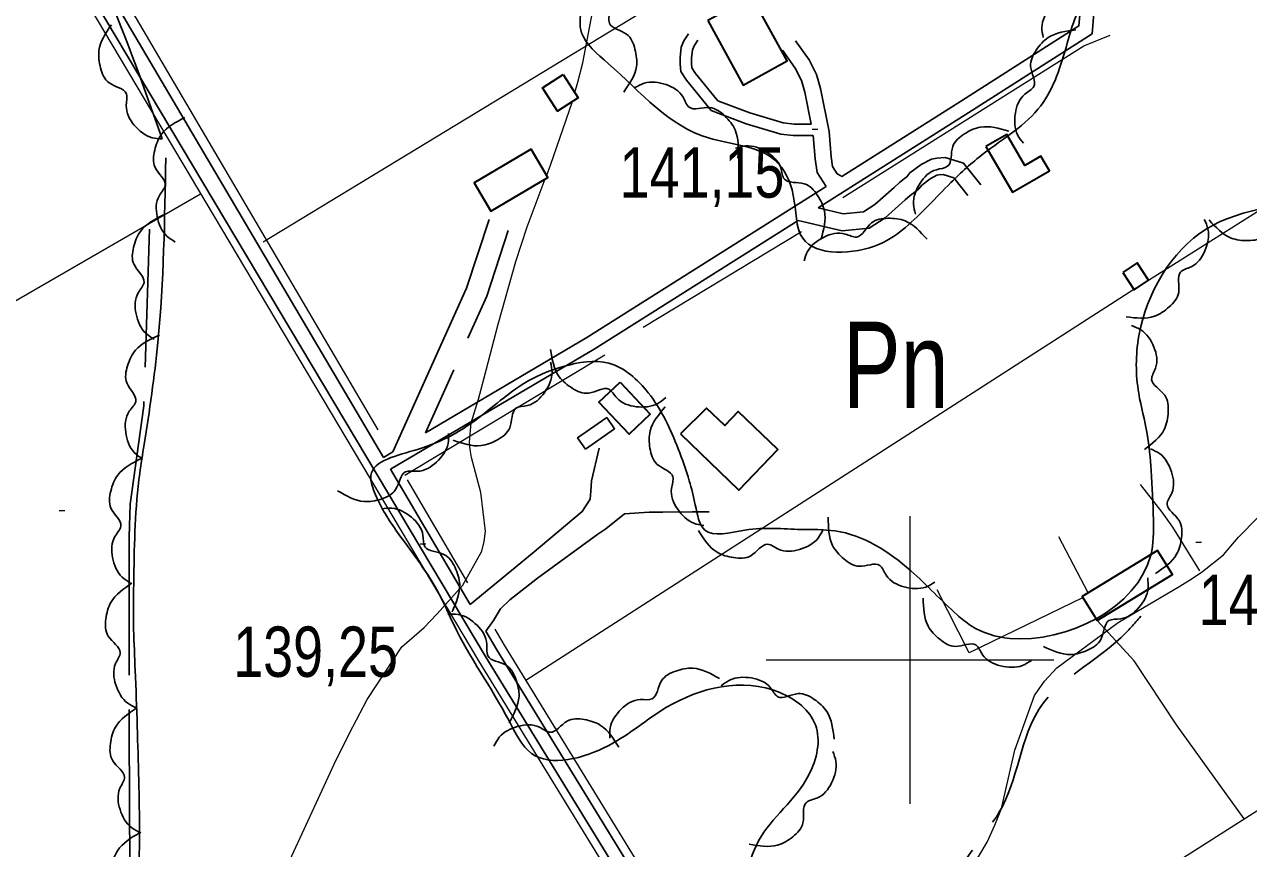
# Model space of a CAD drawing. Extents: x 487425 to 492029, y 4383576 to 4386788.
# Drawn here: x 489846.1 to 490058.8, y 4384467.2 to 4384610.4 of the extents above; entities that cross this region are included whole.
import ezdxf
from ezdxf.enums import TextEntityAlignment as Align

# ---------------------------------------------------------------- set-up
doc = ezdxf.new("R2010")
doc.units = 0
doc.header["$LTSCALE"] = 4
doc.linetypes.add('LONG_DASHED', pattern=[7.5, 6, -1.5])
doc.linetypes.add('MEDIUM_DASHED', pattern=[4.5, 3, -1.5])
for name, color, linetype, lineweight in [('1', 7, 'Continuous', 13), ('21', 7, 'Continuous', 25), ('25', 7, 'LONG_DASHED', 25), ('27', 7, 'Continuous', 25), ('38', 7, 'Continuous', 25), ('47', 7, 'Continuous', 35), ('51', 7, 'Continuous', 13), ('7', 7, 'Continuous', 13), ('9', 7, 'Continuous', 13)]:
    doc.layers.add(name, color=color, linetype=linetype, lineweight=lineweight)
doc.layers.add('31', color=7, linetype='Continuous')

msp = doc.modelspace()

# ---------------------------------------------------------------- linework, layer by layer
at = {"layer": '1'}
for p, q in [((490000, 4384525), (490000, 4384475)), ((489975, 4384500), (490025, 4384500))]:
    msp.add_line(p, q, dxfattribs=at)
at = {"layer": '21'}
msp.add_lwpolyline([(489943.61, 4384536.65), (489948.66, 4384540.16), (489947.3, 4384542.11), (489942.25, 4384538.6)], close=True, dxfattribs=at)
at = {"layer": '25'}
msp.add_lwpolyline([(489867.85, 4384574.89), (489866.85, 4384544.16), (489864.48, 4384527.07), (489864.31, 4384521.37), (489864.28, 4384487.63), (489864.43, 4384462.74), (489866.06, 4384406.72), (489868.32, 4384399.88)], dxfattribs=at)
at = {"layer": '27'}
for points in [[(490039.24, 4384621.99), (490030.98, 4384615.94), (490027.35, 4384607.18), (490022.74, 4384596.32), (490012.75, 4384587.95), (490007.11, 4384582.95), (489999.21, 4384575.17), (489994.7, 4384572.26), (489981.36, 4384573.28), (489979.73, 4384580.78), (489976.53, 4384586.86), (489964.99, 4384590.72), (489947.56, 4384603.67), (489942.93, 4384609.01), (489944, 4384617.78), (489942.39, 4384629.93), (489935.59, 4384637.52), (489917.08, 4384640.2), (489906.73, 4384640.01), (489893.69, 4384640.95), (489890.63, 4384645.38), (489888.39, 4384649.06), (489888.56, 4384656.26), (489891.74, 4384664.95), (489901.13, 4384673.39), (489917.29, 4384683.99), (489924.04, 4384686.22), (489932.9, 4384691.14), (489936.3, 4384697.06), (489937.36, 4384701.78), (489933.07, 4384720.76), (489925.45, 4384731.28), (489926.67, 4384737.05), (489930.36, 4384742.06), (489931.87, 4384747.08), (489928.59, 4384753.24), (489917.34, 4384750.8), (489906.51, 4384739.58), (489897.43, 4384739.54), (489888.53, 4384745.34), (489884.56, 4384748.35), (489882.84, 4384748.8), (489857.62, 4384739.66), (489844.42, 4384736.7), (489833.07, 4384730.21), (489824.8, 4384721.99), (489817.95, 4384713.31), (489818.37, 4384701.61), (489818.42, 4384695.84), (489821.4, 4384688.25), (489822.5, 4384681.5), (489844.21, 4384645.45), (489870.07, 4384590.56)], [(489870.66, 4384587.26), (489869.29, 4384555.17), (489866.91, 4384537.41), (489866.14, 4384532.39), (489865.11, 4384514.39), (489865.09, 4384505.25), (489865.36, 4384498.2), (489865.71, 4384488.45), (489866.1, 4384469.78), (489865.75, 4384451.11), (489865.65, 4384445.04), (489865.57, 4384418.19), (489865.94, 4384414.44), (489867.28, 4384411.14), (489868.24, 4384407.84), (489871.45, 4384404.08), (489875.35, 4384403.62), (489886.45, 4384404.33), (489910.39, 4384412.06), (489923.54, 4384420.42), (489926.77, 4384421.38), (489934.4, 4384418.44), (489939.85, 4384410.02), (489960.76, 4384406.13), (489969.71, 4384415.11), (489972.12, 4384419.52), (489968.92, 4384426.28), (489962.95, 4384436.72), (489961.85, 4384444.15), (489966.37, 4384451.26), (489971.28, 4384462.11), (489973.7, 4384468.55), (489982.43, 4384480), (489983.58, 4384488.69), (489977.37, 4384494.34), (489957.72, 4384491.77), (489947.65, 4384485.13), (489934.23, 4384483.74), (489930.34, 4384489.38), (489920.72, 4384506.13), (489918.26, 4384511.31), (489911.25, 4384521.75), (489907.14, 4384528.66), (489906.33, 4384532.04), (489914.44, 4384536.59), (489925.18, 4384542.18), (489933.75, 4384548.53), (489939.75, 4384550.98), (489947.7, 4384551.56), (489954.51, 4384546.44), (489959.73, 4384536.68), (489961.66, 4384531.12), (489962.7, 4384526.92), (489964.34, 4384522.57), (489971.31, 4384522.55), (489981.06, 4384522.67), (489986.98, 4384522.42), (490000.15, 4384515.49), (490008.23, 4384507.81), (490010.62, 4384505.93), (490017.36, 4384503.74), (490041.85, 4384518.21), (490042.32, 4384524.36), (490041.9, 4384532.91), (490041.24, 4384539.28), (490039.76, 4384546.33), (490039.79, 4384556.31), (490051.47, 4384574.87), (490073.53, 4384581.02), (490095.01, 4384590.63), (490105.59, 4384593.3), (490115.55, 4384591.47), (490124.08, 4384584.62), (490138.17, 4384584.05), (490171.72, 4384593.17), (490181.37, 4384610.46), (490180.13, 4384622.61), (490177.23, 4384630.87), (490160.68, 4384638.79), (490135.19, 4384639.99), (490128.24, 4384646.31), (490116.18, 4384648.6), (490108.61, 4384651.17), (490099.17, 4384653.6), (490092.2, 4384653.55), (490085.22, 4384653.49), (490076.15, 4384653.74), (490069.46, 4384646.19), (490062.38, 4384636.17), (490049.53, 4384628.41), (490039.24, 4384621.99)], [(490023.15, 4384608.17), (490022.94, 4384609.93), (490024.36, 4384613.45), (490027.36, 4384615.59), (490029.37, 4384616.03), (490030.53, 4384619.39), (490032.71, 4384621.43), (490035.58, 4384622.38), (490040.42, 4384621.3)], [(489941.59, 4384618.58), (489943.35, 4384618.36), (489946.43, 4384616.15), (489947.81, 4384612.73), (489947.76, 4384610.67), (489950.75, 4384608.75), (489952.21, 4384606.15), (489952.47, 4384603.14), (489950.27, 4384598.69)], [(489870.07, 4384590.56), (489868.31, 4384590.76), (489865.2, 4384592.94), (489863.8, 4384596.35), (489863.83, 4384598.41), (489860.82, 4384600.3), (489859.34, 4384602.89), (489859.06, 4384605.9), (489861.21, 4384610.37)], [(490019.73, 4384589.79), (490018.71, 4384591.25), (490018.32, 4384595.02), (490019.96, 4384598.32), (490021.53, 4384599.65), (490020.98, 4384603.16), (490021.96, 4384605.98), (490024.04, 4384608.17), (490028.83, 4384609.49)], [(489952.21, 4384599.47), (489953.82, 4384600.22), (489957.61, 4384599.98), (489960.59, 4384597.81), (489961.63, 4384596.04), (489965.19, 4384595.99), (489967.81, 4384594.56), (489969.61, 4384592.14), (489970.11, 4384587.2)], [(489872.33, 4384572.63), (489870.87, 4384573.65), (489869.18, 4384577.04), (489869.56, 4384580.71), (489870.57, 4384582.5), (489868.82, 4384585.6), (489868.75, 4384588.59), (489869.94, 4384591.37), (489873.96, 4384594.27)], [(490000.96, 4384577.47), (490000.61, 4384579.21), (490001.76, 4384582.83), (490004.59, 4384585.2), (490006.55, 4384585.79), (490007.45, 4384589.23), (490009.47, 4384591.43), (490012.26, 4384592.6), (490017.17, 4384591.9)], [(489969.71, 4384588.93), (489971.44, 4384589.32), (489975.09, 4384588.27), (489977.54, 4384585.51), (489978.18, 4384583.56), (489981.64, 4384582.75), (489983.9, 4384580.79), (489985.14, 4384578.04), (489984.56, 4384573.11)], [(490073.34, 4384580.39), (490072.73, 4384578.72), (490069.87, 4384576.22), (490066.22, 4384575.66), (490064.24, 4384576.18), (490061.68, 4384573.71), (490058.81, 4384572.88), (490055.82, 4384573.32), (490051.99, 4384576.47)], [(489868.66, 4384555.74), (489867.2, 4384556.76), (489865.51, 4384560.15), (489865.89, 4384563.82), (489866.9, 4384565.61), (489865.15, 4384568.71), (489865.08, 4384571.7), (489866.27, 4384574.48), (489870.29, 4384577.38)], [(489981.6, 4384569.34), (489982.22, 4384571), (489985.09, 4384573.48), (489988.75, 4384574.02), (489990.73, 4384573.48), (489993.3, 4384575.94), (489996.17, 4384576.75), (489999.16, 4384576.29), (490002.97, 4384573.11)], [(490051.16, 4384576.53), (490051.79, 4384574.87), (490051.26, 4384571.12), (490048.86, 4384568.31), (490047.02, 4384567.4), (490046.71, 4384563.86), (490045.08, 4384561.36), (490042.53, 4384559.74), (490037.57, 4384559.62)], [(489989.6, 4384125.64), (489987, 4384130.58), (489982.08, 4384141.69), (489979.92, 4384147.02), (489978.16, 4384159.7), (489973.47, 4384169.09), (489980.7, 4384182.48), (489983.34, 4384186.9), (489983.36, 4384192.52), (489982.69, 4384195.75), (489981.43, 4384200.85), (489980.85, 4384204.6), (489980.41, 4384208.8), (489980.34, 4384210.3), (489980.8, 4384213.53), (489981.26, 4384218.17), (489983.84, 4384227.99), (490002.63, 4384244.05), (490021.43, 4384259.97), (490028.94, 4384266.17), (490039.61, 4384273.03), (490045.32, 4384277.06), (490056.68, 4384287.6), (490061.57, 4384293.14), (490066.08, 4384299.5), (490085.32, 4384314.13), (490096.9, 4384322.42), (490101.93, 4384325.03), (490109.67, 4384330.78), (490126.57, 4384341.9), (490133.11, 4384345.63), (490146.03, 4384354.21), (490162.33, 4384364.44), (490168.64, 4384368.62), (490171.71, 4384366.58), (490176.18, 4384357.57), (490180.51, 4384351.56), (490183.05, 4384347.8), (490199.13, 4384360.43), (490221.67, 4384374.38), (490243.98, 4384387.66), (490261.64, 4384401.93), (490277.11, 4384409.9), (490279.44, 4384412.07), (490282.52, 4384414.69), (490294.85, 4384423.42), (490298.3, 4384424.09), (490298.38, 4384425.51), (490297.35, 4384431.81), (490292.61, 4384451.1), (490279.32, 4384495.9), (490282.71, 4384502.19), (490283.1, 4384505.48), (490279.52, 4384511.64), (490273.85, 4384520.43), (490270.19, 4384525.99), (490252.78, 4384545.17), (490249.49, 4384550.95), (490249.73, 4384555.37), (490257.19, 4384566.22), (490273.21, 4384559.72), (490278.37, 4384554.16), (490295.94, 4384536.26), (490300.5, 4384532.5), (490304.24, 4384529.04), (490308.8, 4384524.75), (490314.55, 4384517.39), (490319.7, 4384510.55), (490328.97, 4384499.95), (490336.37, 4384491.68), (490340.93, 4384487.01), (490347.72, 4384477.77)], [(490038.5, 4384558.13), (490040.12, 4384557.39), (490042.4, 4384554.36), (490042.68, 4384550.68), (490042.01, 4384548.74), (490044.28, 4384546), (490044.89, 4384543.08), (490044.22, 4384540.13), (490040.79, 4384536.55)], [(489866.57, 4384534.96), (489865.18, 4384536.07), (489863.71, 4384539.56), (489864.33, 4384543.2), (489865.45, 4384544.92), (489863.91, 4384548.13), (489864.03, 4384551.11), (489865.4, 4384553.81), (489869.6, 4384556.45)], [(489957.58, 4384545.62), (489956.16, 4384544.55), (489952.41, 4384544.01), (489949.04, 4384545.53), (489947.66, 4384547.04), (489944.17, 4384546.36), (489941.31, 4384547.22), (489939.04, 4384549.22), (489937.54, 4384553.95)], [(489937.55, 4384551.75), (489937.8, 4384550), (489936.47, 4384546.44), (489933.52, 4384544.22), (489931.53, 4384543.74), (489930.45, 4384540.35), (489928.32, 4384538.26), (489925.47, 4384537.24), (489920.61, 4384538.19)], [(489964.18, 4384523.36), (489962.44, 4384523.75), (489959.59, 4384526.25), (489958.56, 4384529.79), (489958.81, 4384531.83), (489956.03, 4384534.04), (489954.82, 4384536.77), (489954.87, 4384539.79), (489957.49, 4384544.01)], [(489919.82, 4384539.37), (489919.73, 4384537.6), (489917.72, 4384534.38), (489914.39, 4384532.78), (489912.34, 4384532.7), (489910.62, 4384529.59), (489908.12, 4384527.96), (489905.13, 4384527.52), (489900.54, 4384529.41)], [(490041.83, 4384536.68), (490043.4, 4384535.85), (490045.46, 4384532.66), (490045.5, 4384528.97), (490044.7, 4384527.08), (490046.79, 4384524.2), (490047.21, 4384521.24), (490046.34, 4384518.35), (490042.68, 4384515)], [(489864.53, 4384513.36), (489863.08, 4384514.39), (489861.42, 4384517.8), (489861.84, 4384521.47), (489862.87, 4384523.25), (489861.15, 4384526.37), (489861.11, 4384529.35), (489862.32, 4384532.12), (489866.37, 4384534.99)], [(489908.16, 4384526.25), (489909.93, 4384526.38), (489913.37, 4384524.79), (489915.37, 4384521.69), (489915.71, 4384519.66), (489919.01, 4384518.34), (489920.94, 4384516.06), (489921.75, 4384513.14), (489920.44, 4384508.36)], [(490004.33, 4384513.49), (490002.76, 4384512.66), (489998.97, 4384512.69), (489995.88, 4384514.71), (489994.74, 4384516.42), (489991.19, 4384516.27), (489988.49, 4384517.56), (489986.56, 4384519.88), (489985.8, 4384524.78)], [(489984.94, 4384522.72), (489984.06, 4384521.18), (489980.83, 4384519.2), (489977.14, 4384519.26), (489975.27, 4384520.11), (489972.33, 4384518.1), (489969.37, 4384517.77), (489966.49, 4384518.71), (489963.25, 4384522.46)], [(489865.61, 4384491.64), (489864.05, 4384492.48), (489861.98, 4384495.67), (489861.95, 4384499.36), (489862.75, 4384501.25), (489860.67, 4384504.13), (489860.26, 4384507.09), (489861.13, 4384509.99), (489864.79, 4384513.33)], [(490041.32, 4384514.25), (490041.41, 4384512.48), (490039.75, 4384509.07), (490036.61, 4384507.13), (490034.58, 4384506.83), (490033.19, 4384503.56), (490030.87, 4384501.68), (490027.94, 4384500.92), (490023.19, 4384502.33)], [(490021.1, 4384499.9), (490019.55, 4384499.02), (490015.76, 4384498.97), (490012.62, 4384500.9), (490011.44, 4384502.59), (490007.89, 4384502.35), (490005.17, 4384503.58), (490003.18, 4384505.85), (490002.3, 4384510.73)], [(489919.7, 4384507.94), (489921.48, 4384507.9), (489924.77, 4384506.01), (489926.48, 4384502.74), (489926.63, 4384500.69), (489929.8, 4384499.08), (489931.52, 4384496.64), (489932.06, 4384493.66), (489930.33, 4384489.02)], [(489947.84, 4384486.39), (489947.9, 4384488.17), (489949.83, 4384491.43), (489953.13, 4384493.1), (489955.18, 4384493.22), (489956.84, 4384496.37), (489959.3, 4384498.05), (489962.28, 4384498.55), (489966.9, 4384496.75)], [(489967.2, 4384495.48), (489968.66, 4384496.48), (489972.44, 4384496.85), (489975.73, 4384495.18), (489977.04, 4384493.6), (489980.56, 4384494.13), (489983.38, 4384493.14), (489985.55, 4384491.03), (489986.83, 4384486.24)], [(489866.32, 4384469.95), (489864.76, 4384470.8), (489862.72, 4384474), (489862.7, 4384477.69), (489863.51, 4384479.58), (489861.45, 4384482.47), (489861.05, 4384485.43), (489861.93, 4384488.32), (489865.61, 4384491.64)], [(489927.71, 4384485.02), (489928.63, 4384486.54), (489931.91, 4384488.45), (489935.6, 4384488.3), (489937.45, 4384487.42), (489940.43, 4384489.36), (489943.4, 4384489.63), (489946.25, 4384488.62), (489949.41, 4384484.8)], [(489986.6, 4384484.06), (489987.13, 4384482.36), (489986.39, 4384478.64), (489983.83, 4384475.98), (489981.94, 4384475.18), (489981.41, 4384471.67), (489979.64, 4384469.26), (489977, 4384467.8), (489972.04, 4384467.97)], [(489865.69, 4384448.25), (489864.18, 4384449.18), (489862.31, 4384452.48), (489862.49, 4384456.17), (489863.39, 4384458.01), (489861.48, 4384461.01), (489861.24, 4384463.98), (489862.28, 4384466.82), (489866.13, 4384469.95)]]:
    msp.add_spline(points, degree=3, dxfattribs=at)
at = {"layer": '38'}
for p, q in [((489853.76, 4384628.02), (489908.49, 4384535.18)), ((489910.15, 4384536.16), (489908.49, 4384535.18)), ((489923.57, 4384509.6), (489909.71, 4384533.12))]:
    msp.add_line(p, q, dxfattribs=at)
for points in [[(489994.53, 4384389.08), (489991.98, 4384393.38), (489926.25, 4384500.57), (489848.93, 4384630.26)], [(489984.03, 4384578.56), (490010.26, 4384595.12), (490031.65, 4384608.82), (490031.94, 4384612.38), (490030.24, 4384618.25), (490027.31, 4384625.01), (490024.64, 4384627.78)], [(489988.19, 4384584.03), (490008.97, 4384597.14), (490029.36, 4384610.2), (490029.52, 4384612.13), (490027.98, 4384617.44), (490025.28, 4384623.66), (490022.91, 4384626.12)], [(489963.15, 4384607.72), (489962.48, 4384606.7), (489962.21, 4384606.02), (489962.06, 4384604.58), (489962.06, 4384603.64), (489962.12, 4384602.91), (489962.75, 4384601.94), (489966.63, 4384597.15), (489972.16, 4384595.06), (489977.97, 4384593.33), (489979.86, 4384593.11), (489980.82, 4384593.1), (489981.79, 4384593.1), (489982.85, 4384593.1)], [(489988.19, 4384584.03), (489987.98, 4384584.13), (489987.35, 4384584.49), (489986.57, 4384585.73), (489986.32, 4384587.42), (489985.95, 4384591.86), (489984.46, 4384599.32), (489983.75, 4384601.72), (489982.47, 4384604.29), (489980.1, 4384607.59)], [(489984.03, 4384578.56), (489988.41, 4384577.53), (489991.91, 4384577.85), (489993.92, 4384579.17), (489997.24, 4384582.11), (489998.17, 4384582.96), (489999.08, 4384583.64), (489999.44, 4384583.94), (489999.99, 4384584.63), (490001.96, 4384586.1), (490003.72, 4384587.03), (490004.67, 4384587.2), (490006.1, 4384587.29), (490009.32, 4384586.32), (490012.35, 4384582.56)], [(489915.79, 4384539.48), (489943.85, 4384556.03), (489985.43, 4384582.28)], [(489909.71, 4384533.12), (489945.1, 4384553.99), (489980.56, 4384576.38)], [(489910.15, 4384536.16), (489922.95, 4384564.59), (489926.85, 4384576.55)], [(489923.57, 4384509.6), (489934.33, 4384518.46), (489943.05, 4384525.78), (489944.41, 4384527.95), (489944.56, 4384529.3), (489944.64, 4384531.1), (489946.01, 4384536.79)], [(489926.28, 4384505.01), (489927.62, 4384506.86), (489928.83, 4384508.88), (489930.48, 4384510.45), (489935.29, 4384514.18), (489945.74, 4384521.87), (489947.17, 4384522.77), (489950.4, 4384525.38), (489954.67, 4384525.67), (489957.07, 4384525.66), (489962.17, 4384525.72), (489965.1, 4384525.71)], [(490018.58, 4384353.17), (489993.93, 4384394.56), (489928.2, 4384501.76), (489926.28, 4384505.01)]]:
    msp.add_lwpolyline(points, dxfattribs=at)
at = {"layer": '38', "linetype": 'MEDIUM_DASHED'}
for points in [[(489961.49, 4384608.8), (489960.72, 4384607.61), (489960.27, 4384606.5), (489960.08, 4384604.69), (489960.08, 4384603.56), (489960.19, 4384602.25), (489961.14, 4384600.78), (489965.43, 4384595.49), (489971.52, 4384593.19), (489977.57, 4384591.39), (489979.73, 4384591.13), (489980.81, 4384591.12), (489981.79, 4384591.12), (489983.21, 4384591.12)], [(489982.85, 4384593.1), (489981.74, 4384598.65), (489981.14, 4384600.7), (489980.07, 4384602.84), (489977.83, 4384605.96)], [(489985.43, 4384582.28), (489983.9, 4384584.74), (489983.55, 4384587.09), (489983.21, 4384591.12)], [(489980.56, 4384576.38), (489988.2, 4384574.58), (489992.91, 4384575.01), (489995.7, 4384576.85), (489999.19, 4384579.94), (490000.03, 4384580.7), (490000.9, 4384581.35), (490001.55, 4384581.9), (490002.04, 4384582.52), (490003.52, 4384583.62), (490004.69, 4384584.24), (490005.03, 4384584.3), (490005.76, 4384584.34), (490007.61, 4384583.79), (490010.07, 4384580.73)], [(489915.79, 4384539.48), (489926.48, 4384563.22), (489930.45, 4384575.38)]]:
    msp.add_lwpolyline(points, dxfattribs=at)
at = {"layer": '38', "linetype": 'LONG_DASHED'}
msp.add_spline([(489979.03, 4384423.32), (489992.13, 4384440.38), (490004.4, 4384457.29), (490012.84, 4384469.71), (490015.47, 4384473.45), (490022.73, 4384491.87), (490036.71, 4384503.9), (490040.1, 4384507.57)], degree=3, dxfattribs=at)
at = {"layer": '47'}
for points in [[(489964.9, 4384611.12), (489971.04, 4384599.91), (489978.68, 4384604.1), (489972.54, 4384615.31)], [(489939.76, 4384601.75), (489942.37, 4384597.7), (489938.76, 4384595.38), (489936.15, 4384599.43)], [(490013.2, 4384589.23), (490017.82, 4384581.27), (490024.26, 4384585), (490022.77, 4384587.55), (490019.99, 4384585.93), (490016.86, 4384591.29)], [(489934.17, 4384588.79), (489924.25, 4384582.94), (489927.16, 4384578.01), (489937.08, 4384583.86)], [(490036.98, 4384567.34), (490038.95, 4384564.32), (490041.47, 4384565.97), (490039.5, 4384568.99)], [(489949.64, 4384548.26), (489954.87, 4384542.72), (489951.19, 4384539.25), (489945.96, 4384544.79)], [(489960.11, 4384539.3), (489970.28, 4384529.52), (489977.04, 4384536.55), (489970.17, 4384543.15), (489967.84, 4384540.73), (489964.67, 4384543.76)], [(490032.52, 4384506.84), (490045.61, 4384514.85), (490043.05, 4384519.03), (490029.96, 4384511.02)]]:
    msp.add_lwpolyline(points, close=True, dxfattribs=at)
at = {"layer": '51'}
for p, q in [((489853.04, 4384632.81), (489907.53, 4384539.97)), ((489713.73, 4384487.03), (489876.69, 4384580.98)), ((489953.65, 4384557.84), (489981.14, 4384574.48)), ((489946.96, 4384552.99), (489912.19, 4384532.03)), ((489912.63, 4384531.27), (489923.12, 4384513.41)), ((490030.99, 4384511.65), (490025.89, 4384521.41))]:
    msp.add_line(p, q, dxfattribs=at)
for points in [[(490293.97, 4384828.31), (490202.7, 4384771.46), (490166.71, 4384748.1), (490064.7, 4384684.22), (490001.36, 4384641.75), (489887.58, 4384572.63)], [(489978.9, 4384421.96), (490088.78, 4384491.9), (490196.29, 4384561.76), (490306.27, 4384632.13), (490420.33, 4384703.9)], [(490195.4, 4384664.63), (490165.2, 4384644.03), (490039.92, 4384564.96), (490038.94, 4384564.35), (489933.25, 4384496.41)], [(489847.88, 4384629.61), (489925.01, 4384499.82), (489990.7, 4384392.68)], [(489988.35, 4384580.38), (490030.2, 4384606.72), (490034.78, 4384608.58)], [(490050.39, 4384515.48), (490045.69, 4384523.07), (490043.82, 4384525.7), (490040.09, 4384530.51)], [(490030.08, 4384510.84), (490010.31, 4384501.21), (490004.72, 4384512.17)], [(490058.06, 4384472.35), (490046.34, 4384488.73), (490038.95, 4384499.85), (490032.52, 4384506.84)], [(489927.87, 4384505.32), (489929.49, 4384502.54), (489995.22, 4384395.34), (490017.98, 4384357.13)]]:
    msp.add_lwpolyline(points, dxfattribs=at)
at = {"layer": '7'}
for p, q in [((489983.02, 4384592.24), (489984.02, 4384592.24)), ((489852.13, 4384525.98), (489853.13, 4384525.98)), ((489914.87, 4384520.17), (489915.87, 4384520.17)), ((490049.68, 4384520.43), (490050.68, 4384520.43))]:
    msp.add_line(p, q, dxfattribs=at)
at = {"layer": '9'}
for points in [[(489941.78, 4384598.61), (489942.29, 4384600.43), (489943.13, 4384603.79), (489945.56, 4384616.6)], [(489936.87, 4384584.22), (489937.52, 4384585.96), (489941.34, 4384597.04)], [(489887.02, 4384453.87), (489900.31, 4384482.64), (489903.17, 4384488.38), (489905.66, 4384493.14), (489911.68, 4384502.28), (489915.55, 4384505.65), (489916.69, 4384506.77), (489917.85, 4384507.98), (489922.29, 4384513.01), (489925.58, 4384518.87), (489926.02, 4384520.59), (489926.26, 4384522.35), (489925.41, 4384529.08), (489923.83, 4384535.2), (489923.6, 4384536.58), (489923.47, 4384537.82), (489923.75, 4384541.19), (489925, 4384545.32), (489925.48, 4384547.06), (489926.01, 4384549.04), (489928.43, 4384558.35), (489931.52, 4384569.25), (489932.48, 4384572.25), (489933.49, 4384575.24), (489936.63, 4384583.6)], [(490007.03, 4384457.61), (490013.45, 4384468.34), (490014.77, 4384471.25), (490015.89, 4384474.14), (490018.25, 4384484.33), (490021.63, 4384493.83), (490023.4, 4384496.28), (490025.52, 4384498.64), (490036.17, 4384506.52), (490046.89, 4384512.8), (490049.05, 4384514.15), (490050.86, 4384515.34), (490054.51, 4384518.27), (490056.41, 4384520.53), (490057.13, 4384521.31), (490057.92, 4384522.16), (490061.46, 4384525.76)]]:
    msp.add_lwpolyline(points, dxfattribs=at)

# ---------------------------------------------------------------- texts
at = {"layer": '31', "width": 0.75}
msp.add_text('Pn', height=15, dxfattribs=at).set_placement((489997.55, 4384543.78), align=Align.CENTER)
at = {"layer": '7', "width": 0.8}
for s, p in [('141,15', (489949.55, 4384580.34)), ('144,66', (490050.18, 4384506.06)), ('139,25', (489882.39, 4384497.05))]:
    msp.add_text(s, height=8.75, dxfattribs=at).set_placement(p)

doc.saveas('drawing.dxf')
